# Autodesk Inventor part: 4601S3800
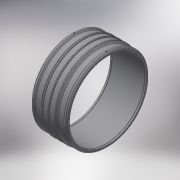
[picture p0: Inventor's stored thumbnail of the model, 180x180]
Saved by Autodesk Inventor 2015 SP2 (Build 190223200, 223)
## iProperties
Created: 2017-06
Part Number: 4601S3800
Material: Generic
Description: PLASSON SUPER LIGHTFIT 800 MM
Document SubType Name: Modeling
Designer: KIM
Mass: 31397.9 g
Surface Area: 23827.3 cm^2
Volume: 31397.9 cm^3
Density: 1 g/cm^3
Appearance: Default
Author: KIM
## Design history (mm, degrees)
derived "4601S3.ipt"
feature "Solid1::4601S3.ipt"
tag "TaggingFeature1"
body "Solid1"
other parameters: "d14" = 17.6296, "d19" = 3.52592, "d20" = 168 deg, "d22" = 876, "d23" = 876, "d24" = 849.72, "d25" = 135 deg, "d27" = 135 deg, "d29" = 438, "d35" = 15, "d39" = 0, "d40" = 4, "d41" = 14, "d42" = 0, "d43" = 135 deg, "d44" = 44, "d45" = 16, "d46" = 16, "d47" = 16, "d48" = 858.48, "d49" = 876, "d50" = 4.38, "d51" = 6, "d52" = 0, "D_" = 876, "A_" = 438, "d_2" = 12
